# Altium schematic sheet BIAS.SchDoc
size A3; Date: Not shown in title block; ApprovedBy: Not shown in title block; CheckedBy: Not shown in title block; Author: Not shown in title block; CompanyName: Not shown in title block; Engineer: Not shown in title block; Organization: Not shown in title block; Address1: Not shown in title block; Address2: Not shown in title block; Address3: Not shown in title block; Address4: Not shown in title block; DocumentNumber: 1; Revision: Use project parameter SCH_Rev; SheetNumber: 3; SheetTotal: 3; PageSetup: Record=PageOptions¦CenterHorizontal=True¦CenterVertical=True¦PrintScale=0.93¦XCorrection=1.00¦YCorrection=1.00¦PrintKind=0¦BorderSize=5000000¦LeftOffset=0¦BottomOffset=0¦Orientation=2¦PaperLength=1000¦PaperWidth=1000¦Scale=100¦PaperSource=15¦PrintQuality=600¦MediaType=1¦DitherType=10¦PaperKind=Letter¦PrintScaleMode=1
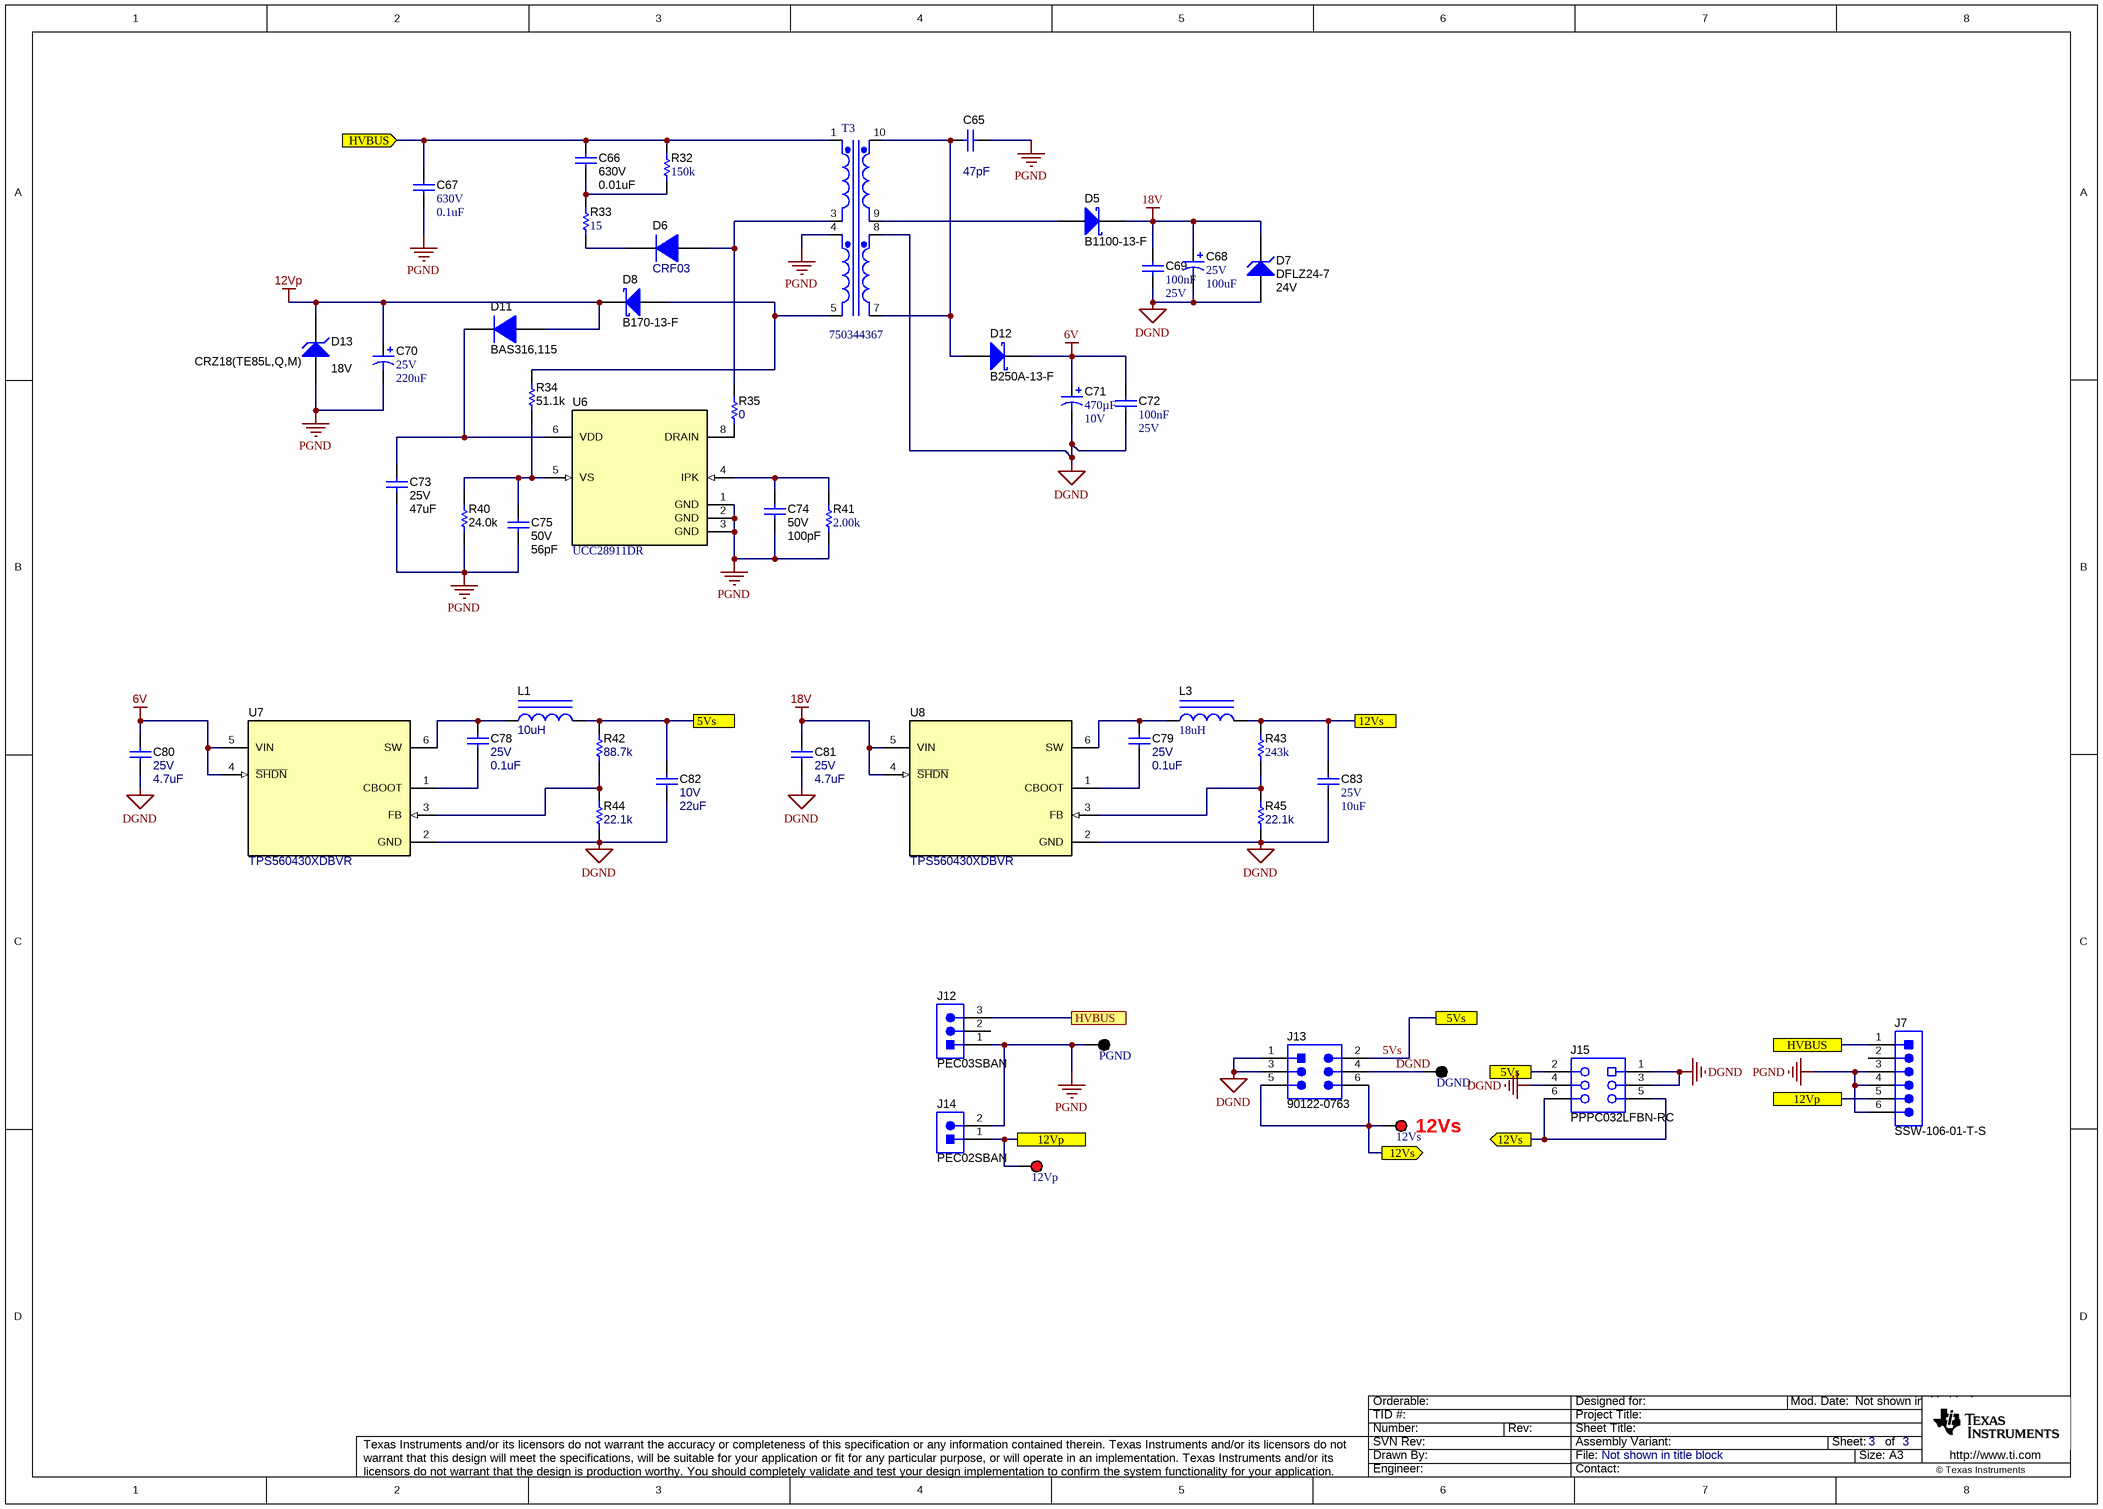
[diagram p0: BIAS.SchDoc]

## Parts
12Vp  5000  [Keystone5000]  (value not drawn)
12Vs  5000  [Keystone5000]  (value not drawn)
C65  ValueDisplayed: 47pF  [KY_700x500x1000]  (hidden comment: DE11XKX470JN4AC05F)
C66  VDC_V: 630V  ValueDisplayed: 0.01uF  [1206]  (hidden comment: GRM31BR72J103KW01L)
C67  VDC_V: 630V  ValueDisplayed: 0.1uF  [1210_280]  (hidden comment: C1210C104KBRAC7800)
C68  VDC_V: 25V  ValueDisplayed: 100uF  [SVPF_E7]  (hidden comment: 25SVPF100M)
C69  Cap_F: 100nF  VDC_V: 25V  [0603]  (hidden comment: GCJ188R71E104KA12D)
C70  VDC_V: 25V  ValueDisplayed: 220uF  [Panasonic_D8]  (hidden comment: EEEFTE221XAP)
C71  ValueDisplayed: 470µF  VDC_V: 10V  [Panasonic_D8]  (hidden comment: EEE-FTA471XAP)
C72  Cap_F: 100nF  VDC_V: 25V  [0603]  (hidden comment: GCJ188R71E104KA12D)
C73  VDC_V: 25V  ValueDisplayed: 47uF  [1206]  (hidden comment: C3216JB1E476M160AC)
C74  VDC_V: 50V  ValueDisplayed: 100pF  [0603]  (hidden comment: C0603C101J5GAC)  (no BOM)
C75  VDC_V: 50V  ValueDisplayed: 56pF  [0603]  (hidden comment: GRM1885C1H560JA01D)  (no BOM)
C78  VDC_V: 25V  ValueDisplayed: 0.1uF  [0603]  (hidden comment: C1608X7R1E104K080AA)
C79  VDC_V: 25V  ValueDisplayed: 0.1uF  [0603]  (hidden comment: C1608X7R1E104K080AA)
C80  VDC_V: 25V  ValueDisplayed: 4.7uF  [0603]  (hidden comment: GRM188R61E475KE11D)
C81  VDC_V: 25V  ValueDisplayed: 4.7uF  [0603]  (hidden comment: GRM188R61E475KE11D)
C82  VDC_V: 10V  ValueDisplayed: 22uF  [0603]  (hidden comment: C1608X5R1A226M080AC)
C83  VDC_V: 25V  ValueDisplayed: 10uF  [0603]  (hidden comment: GRT188R61E106ME13D)
D5  B1100-13-F  [SMA]
D6  CRF03  [SOD-123H]
D7  DFLZ24-7  value 24V  [PowerDI123]
D8  B170-13-F  [SMA]
D11  BAS316,115  [SOD-323]
D12  B250A-13-F  [SMA]
D13  CRZ18(TE85L,Q,M)  value 18V  [SOD-123]
DGND  5001  [Keystone5001]  (value not drawn)
J7  SSW-106-01-T-S  [Samtec_SSW-106-01-x-S]
J12  PEC03SBAN  [Sullins_PEC03SBAN]
J13  90122-0763  [Molex_90122-0763]
J14  PEC02SBAN  [Sullins_xxC02SBAN]
J15  PPPC032LFBN-RC  [Sullins_xxxC032LFBN-RC]
L1  ValueDisplayed: 10uH  [VLS252010HBX]  (hidden comment: 74438323100)
L3  ValueDisplayed: 18uH  [WE-PD2A_4532]  (hidden comment: 784773118)
PGND  5001  [Keystone5001]  (value not drawn)
R32  ValueDisplayed: 150k  [1206]  (hidden comment: CRCW1206150KFKEA)
R33  ValueDisplayed: 15  [0603]  (hidden comment: CRCW060315R0JNEA)
R34  ValueDisplayed: 51.1k  [0603]  (hidden comment: RC0603FR-0751K1L)
R35  ValueDisplayed: 0  [0603]  (hidden comment: RC0603JR-070RL)
R40  ValueDisplayed: 24.0k  [0603]  (hidden comment: RC0603FR-0724KL)
R41  ValueDisplayed: 2.00k  [0603]  (hidden comment: ERJ3EKF2001V)
R42  ValueDisplayed: 88.7k  [0603]  (hidden comment: CRCW060388K7FKEA)
R43  ValueDisplayed: 243k  [0603]  (hidden comment: RT0603BRD07243KL)
R44  ValueDisplayed: 22.1k  [0603]  (hidden comment: CRCW060322K1FKEA)
R45  ValueDisplayed: 22.1k  [0603]  (hidden comment: CRCW060322K1FKEA)
T3  750344367  [Wurth_750315894]
U6  UCC28911DR  [D0007A_N]
U7  TPS560430XDBVR  [DBV0006A_N]
U8  TPS560430XDBVR  [DBV0006A_N]

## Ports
5Vs, 12Vp, 12Vs, 12Vs (out), HVBUS, HVBUS (in)

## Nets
6V: C71.1(+) C72.1 C80.1 D12.1(K) U7.4(~{SHDN}) U7.5(VIN)
12Vp: C70.1(+) D8.1(K) D11.2(A) D13.1(K)
18V: C68.1(+) C69.1 C81.1 D5.1(K) D7.1(K) U8.4(~{SHDN}) U8.5(VIN)
DGND: C68.2(-) C69.2 C71.2(-) C72.2 C80.2 C81.2 C82.2 C83.2 D7.2(A) DGND.1 J13.1 J13.3 J13.4 J15.1 J15.3 J15.4 R44.1 R45.1 T3.8(Sec2+) U7.2(GND) U8.2(GND)
PGND: C65.2 C67.2 C70.2(-) C73.2 C74.2 C75.2 D13.2(A) J7.3 J7.4 J7.6 J12.1 J14.2 PGND.1 R40.1 R41.1 T3.4(Pri2+) U6.1(GND) U6.2(GND) U6.3(GND)
5Vs: C82.1 J13.2 J15.2 L1.2 R42.2 ; port 5Vs
12Vp: 12Vp.1 J7.5 J14.1 ; port 12Vp  [a separate net that carries the same name]
12Vs: 12Vs.1 C83.1 J13.5 J13.6 J15.5 J15.6 L3.2 R43.2 ; port 12Vs
HVBUS: C66.1 C67.1 J7.1 J12.3 R32.2 T3.1(Pri1+) ; port HVBUS
NetC65_1: C65.1 D12.2(A) T3.7(Sec2-) T3.10(Sec1+)
NetC66_2: C66.2 R32.1 R33.2
NetC73_1: C73.1 D11.1(K) U6.6(VDD)
NetC74_1: C74.1 R41.2 U6.4(IPK)
NetC75_1: C75.1 R34.1 R40.2 U6.5(VS)
NetC78_1: C78.1 L1.1 U7.6(SW)
NetC78_2: C78.2 U7.1(CBOOT)
NetC79_1: C79.1 L3.1 U8.6(SW)
NetC79_2: C79.2 U8.1(CBOOT)
NetD5_2: D5.2(A) T3.9(Sec1-)
NetD6_1: D6.1(K) R33.1
NetD6_2: D6.2(A) R35.2 T3.3(Pri1-)
NetD8_2: D8.2(A) R34.2 T3.5(Pri2-)
NetR35_1: R35.1 U6.8(DRAIN)
NetR42_1: R42.1 R44.2 U7.3(FB)
NetR43_1: R43.1 R45.2 U8.3(FB)

Not connected (* = marked no-connect by the designer): J7 2; J12 2

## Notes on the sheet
- 12Vs

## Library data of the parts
12Vp 12Vs = CMP-0055137-1: Test Point, Miniature, Red, TH; Manufacturer: Keystone; ContactFinish: Silver; Green_Lifecycle: Active; Green_REACh: Passed; CNHeader: FALSE; CT: TRUE
C65 = CMP-0009608-4: CAP, CERM, 47 pF, X1 250 VAC/Y1 300 VAC, +/- 10%, B, TH; Manufacturer: MuRata; TaMin_C: -25°C; Polarized: N; SizeAreaWB_mm2: 66.5; Value1: Unknown; U/M: EA; Value: 47pF; TaMax_C: 85°C; SizeZ_mm: 13; SizeX_mm: 9; SizeY_mm: 5; Cap_Case: 7x5x10mm; SizeArea_mm2: 37.5; AEC Category: Q200; AC_Safety: X1Y2; VAC_X: 250V; VAC_Y: 300V
C66 = CMP-0008910-2: CAP, CERM, 0.01 uF, 630 V, +/- 10%, X7R, 1206; Manufacturer: MuRata; TaMin_C: -55°C; Polarized: N; SizeAreaWB_mm2: 10.92; Value1: Unknown; U/M: EA; Value: 0.01uF; TaMax_C: 125°C; SizeZ_mm: 1.35; SizeX_mm: 3.2; SizeY_mm: 1.6; SizeArea_mm2: 5.12; Cap_F: 10nF; AEC Category: Q200
C67 = CMP-0009076-1: CAP, CERM, 0.1 uF, 630 V, +/- 10%, X7R, 1210; Manufacturer: Kemet; TaMin_C: -55°C; Polarized: N; SizeAreaWB_mm2: 14.7; Value1: Unknown; U/M: EA; Value: 0.1uF; TaMax_C: 125°C; SizeZ_mm: 2.8; SizeX_mm: 3.2; SizeY_mm: 2.5; Cap_Case: 1210; SizeArea_mm2: 8; Cap_F: 100nF; AEC Category: Q200
C68 = CMP-0012117-3: CAP, Aluminum Polymer, 100 uF, 25 V, +/- 20%, 0.024 ohm, 8.0x7.0mm SMD; Manufacturer: Panasonic; TaMin_C: -55°C; ESR_ohm: 24m; Polarized: Y; Value: 100uF; TaMax_C: 105°C; CompType: Capacitor; Cap_F: 100µF; IRMS_A: 3.2A; AEC Category: Q200
C69 C72 = CMP-0007404-4: CAP, CERM, 0.1 uF, 25 V, +/- 10%, X7R, 0603; Manufacturer: MuRata; TaMin_C: -55°C; Polarized: N; SizeAreaWB_mm2: 4.68; Value1: Unknown; U/M: EA; Value: 0.1uF; TaMax_C: 125°C; SizeZ_mm: 1; SizeX_mm: 1.6; SizeY_mm: 0.8; SizeArea_mm2: 1.28; AEC Category: Q200
C70 = CMP-0010738-1: CAP, AL, 220 uF, 25 V, +/- 20%, 0.16 ohm, AEC-Q200 Grade 2, SMD; Manufacturer: Panasonic; TaMin_C: -55°C; ESR_ohm: 0.16; Polarized: Y; SizeAreaWB_mm2: 73.96; U/M: EA; Value: 220uF; TaMax_C: 105°C; SizeZ_mm: 8; SizeX_mm: 6.6; Cap_Case: 6.3x7.7mm; SizeArea_mm2: 43.56; CompType: Capacitor; Cap_F: 220µF; IRMS_A: 600mA; AEC Grade: 2; AEC Category: Q200
C71 = CMP-0084632-1: CAP, AL, 470 µF, 10 V, +/- 20%, 0.16 ohm, AEC-Q200 Grade 2, SMD; Manufacturer: Panasonic; U/M: EA; SizeArea_mm2: 43.56; ESR_ohm: 0.16; AEC Category: Q200; SizeY_mm: 6.6; Value: 470uF; TaMin_C: -55°C; TaMax_C: 105°C; SizeAreaWB_mm2: 73.96; CompType: Capacitor; AEC Qualified: Y; Cap_Case: 6.6x6.6x8mm; AEC Grade: 2; SizeZ_mm: 8
C73 = CMP-0008646-2: CAP, CERM, 47 uF, 25 V, +/- 20%, JB, 1206; Manufacturer: TDK; TaMin_C: -55°C; Polarized: N; SizeAreaWB_mm2: 10.92; Value1: Unknown; U/M: EA; Value: 47uF; TaMax_C: 85°C; SizeZ_mm: 1.35; SizeX_mm: 3.2; SizeY_mm: 1.6; SizeArea_mm2: 5.12; Cap_F: 47µF; AEC Category: Q200
C74 = CMP-0006840-4: CAP, CERM, 100 pF, 50 V, +/- 5%, C0G/NP0, 0603; Manufacturer: Kemet; TaMin_C: -55°C; Polarized: N; SizeAreaWB_mm2: 4.68; Value1: Unknown; U/M: EA; Value: 100pF; TaMax_C: 125°C; SizeZ_mm: 1; SizeX_mm: 1.6; SizeY_mm: 0.8; SizeArea_mm2: 1.28; AEC Category: Q200
C75 = CMP-0007224-4: CAP, CERM, 56 pF, 50 V, +/- 5%, C0G/NP0, 0603; Manufacturer: MuRata; TaMin_C: -55°C; Polarized: N; SizeAreaWB_mm2: 4.68; Value1: Unknown; U/M: EA; Value: 56pF; TaMax_C: 125°C; SizeZ_mm: 1; SizeX_mm: 1.6; SizeY_mm: 0.8; SizeArea_mm2: 1.28; AEC Category: Q200
C78 C79 = CMP-0007039-5: CAP, CERM, 0.1 uF, 25 V, +/- 10%, X7R, 0603; Manufacturer: TDK; TaMin_C: -55°C; Polarized: N; SizeAreaWB_mm2: 4.68; Value1: Unknown; U/M: EA; Value: 0.1uF; TaMax_C: 125°C; SizeZ_mm: 1; SizeX_mm: 1.6; SizeY_mm: 0.8; SizeArea_mm2: 1.28; Cap_F: 100nF; AEC Category: Q200
C80 C81 = CMP-0007347-1: CAP, CERM, 4.7 uF, 25 V, +/- 10%, X5R, 0603; Manufacturer: MuRata; TaMin_C: -55°C; Polarized: N; SizeAreaWB_mm2: 4.68; Value1: Unknown; U/M: EA; Value: 4.7uF; TaMax_C: 85°C; SizeZ_mm: 1; SizeX_mm: 1.6; SizeY_mm: 0.8; SizeArea_mm2: 1.28; Cap_F: 4.7µF; AEC Category: Q200
C82 = CMP-0007005-1: CAP, CERM, 22 uF, 10 V, +/- 20%, X5R, 0603; Manufacturer: TDK; TaMin_C: -55°C; ESR_ohm: 3.71m; Polarized: N; SizeAreaWB_mm2: 4.68; Value1: 0.00371 ohm; U/M: EA; Value: 22uF; TaMax_C: 85°C; SizeZ_mm: 1; SizeX_mm: 1.6; SizeY_mm: 0.8; SizeArea_mm2: 1.28; Cap_F: 22µF; IRMS_A: 2.69936A; AEC Category: Q200
C83 = CMP-0007501-4: CAP, CERM, 10 uF, 25 V, +/- 20%, X5R, 0603; Manufacturer: MuRata; TaMin_C: -55°C; Polarized: N; SizeAreaWB_mm2: 4.68; Value1: Unknown; U/M: EA; Value: 10uF; TaMax_C: 85°C; SizeZ_mm: 1; SizeX_mm: 1.6; SizeY_mm: 0.8; SizeArea_mm2: 1.28; Cap_F: 10µF; AEC Category: Q200
D5 = CMP-0028371-1: Diode, Schottky, 100 V, 1 A, SMA; Manufacturer: Diodes Inc.; Io_A: 1A; Green_Lifecycle: Active; SizeAreaWB_mm2: 37.3428; Vr_V: 100V; Green_REACh: Passed; TJmax_C: 150°C; U/M: EA; Value: 100V; SizeZ_mm: 2.87; SizeX_mm: 5.59; SizeY_mm: 2.92; Vf_V: 790mV; Value2: 0.79V; SizeArea_mm2: 16.3228; AEC Category: Q101; RJC_CperW: 25
D6 = CMP-0077074-2: Diode, Superfast Rectifier, 600 V, 1 A, 3.5x1.6mm; Manufacturer: Toshiba; Value: 600V; SizeY_mm: 1.6; Value2: 1.7V; Value1: 1A; Io_A: 0.7A; Green_Lifecycle: Not Set; AEC Category: Q101; SizeX_mm: 3.5; SizeAreaWB_mm2: 11.7; SizeZ_mm: 1.0; Green_REACh: Incomplete; SizeArea_mm2: 5.6; TJmax_C: 150°C; AEC Qualified: N
D7 = CMP-0005415-4: Diode, Zener, 24 V, 1 W, PowerDI123; Manufacturer: Diodes Inc.; Power_W: 1W; RJA_CperW: 110; SizeAreaWB_mm2: 13.066; SizeZ_mm: 0.98; SizeX_mm: 3.7; AEC Category: Q101; SizeY_mm: 1.78; SizeArea_mm2: 6.586
D8 = CMP-0028391-2: Diode, Schottky, 70 V, 1 A, SMA; Manufacturer: Diodes Inc.; SizeAreaWB_mm2: 37.3428; RJC_CperW: 25; Io_A: 1A; AEC Category: Q101; Green_Lifecycle: Active; SizeZ_mm: 2.87; Value: 70V; Vf_V: 7.9dV; SizeY_mm: 2.92; Green_REACh: Passed; Value2: 0.79V; SizeX_mm: 5.59; TJmax_C: 150°C; SizeArea_mm2: 16.3228
D11 = CMP-0029006-1: Diode, Ultrafast, 100 V, 0.25 A, SOD-323; Manufacturer: Nexperia; Io_A: 250mA; Green_Lifecycle: Not Set; SizeAreaWB_mm2: 8.695; Vr_V: 100V; Green_REACh: Incomplete; Value1: 0.25A; TJmax_C: 150°C; U/M: EA; Value: 100V; SizeZ_mm: 1; SizeX_mm: 2.7; SizeY_mm: 1.35; Vf_V: 1.4V; SizeArea_mm2: 3.645; AEC Category: Q101
D12 = CMP-0028405-2: Diode, Schottky, 50 V, 2 A, SMA; Manufacturer: Diodes Inc.; SizeArea_mm2: 16.3228; RJC_CperW: 20; Vr_V: 50V; SizeX_mm: 5.59; Green_REACh: Incomplete; SizeY_mm: 2.92; Green_Lifecycle: Not Set; Value2: 0.7V; Io_A: 2A; Value: 50V; SizeZ_mm: 2.87; SizeAreaWB_mm2: 37.3428; AEC Category: Q101; TJmax_C: 150°C; Vf_V: 7dV
D13 = CMP-0005747-4: Diode, Zener, 18 V, 700 mW, SOD-123; Manufacturer: Toshiba; SizeAreaWB_mm2: 13.095; SizeArea_mm2: 6.545; SizeX_mm: 3.85; Value1: 0.7W; SizeY_mm: 1.7; Power_W: 700mW; SizeZ_mm: 1.35; RJA_CperW: 340; AEC Category: Q101
DGND PGND = CMP-0055138-1: Test Point, Miniature, Black, TH; Manufacturer: Keystone; ContactFinish: Silver; Green_Lifecycle: Active; Green_REACh: Passed; CNHeader: FALSE; CT: TRUE
J7 = CMP-0075621-1: Receptacle, 6x1, 2.54mm, Tin, TH; Manufacturer: Samtec; Pitch_mm: 2.54; Gender: Female; Cert_CSA: Y; Current_A: 5.7A; CT: False; Row_Count: 1
J12 = CMP-0054704-1: Header, 100mil, 3x1, Tin, R/A, TH; Manufacturer: Sullins Connector Solutions; CNHeader: FALSE; Current_A: 3A; Green_Lifecycle: Not Set; Shrouded: N; Gender: Male; Green_REACh: Incomplete; Voltage_V: 1.8kV; Row_Count: 1; Pitch_mm: 2.54; Cert_UL: Y
J13 = CMP-0077741-2: Header, 2.54mm, 3x2, Gold, R/A, TH; Manufacturer: Molex; Pitch_mm: 2.54; Gender: Male; Cert_UL: Y; Current_A: 3A; Voltage_V: 350V; Shrouded: N; Row_Count: 2
J14 = CMP-0054712-1: Header, 2.54 mm, 2x1, Tin, R/A, TH; Manufacturer: Sullins Connector Solutions; CNHeader: FALSE; Current_A: 3A; Shrouded: N; Gender: Male; Voltage_V: 1.8kV; Row_Count: 1; Pitch_mm: 2.54; Cert_UL: Y
J15 = CMP-0082513-1: Receptacle, 2.54mm, 3x2, Gold, TH; Manufacturer: Sullins Connector Solutions; Pitch_mm: 2.54; Gender: Female; Cert_UL: Y; Voltage_V: 250V; Current_A: 3A; Row_Count: 2; CompType: Socket Strip
L1 = CMP-0063086-1: Inductor, Wirewound, Ferrite, 10 uH, 0.68 A, 0.46 ohm, SMD; Manufacturer: Würth Elektronik; Isat: 1.35A @ 20% inductance drop; Irms: 0.60A @ 40C rise; Green_Lifecycle: Active; SizeAreaWB_mm2: 10.5; DCR_ohm: 0.46; Green_REACh: Passed; Value1: 0.843 ohm; Value: 10uH; Imax_A: 600mA; SizeZ_mm: 1; SizeX_mm: 2.5; SizeY_mm: 2; Value2: 0.6A; SizeArea_mm2: 5; Ind_H: 10µH; AEC Qualified: N; AEC Category: Q200
L3 = CMP-0064687-1: Inductor, Wirewound, Ferrite, 18 uH, 1.1 A, 0.225 ohm, AEC-Q200 Grade 1, SMD; Manufacturer: Wurth Elektronik; Isat: 1.29A @ 20% inductance drop; Irms: 1.1A @ 40C rise; Green_Lifecycle: Active; SizeAreaWB_mm2: 27.5; DCR_ohm: 0.225; Green_REACh: Passed; Value: 18uH; Imax_A: 1.1A; SizeZ_mm: 3.5; SizeX_mm: 4; SizeY_mm: 4.5; SizeArea_mm2: 18; Ind_H: 18µH; AEC Qualified: Y; AEC Grade: 1; AEC Category: Q200
R32 = CMP-0016639-3: RES, 150 k, 1%, 0.25 W, AEC-Q200 Grade 0, 1206; Manufacturer: Vishay-Dale; Power_W: 250mW; TempCo: 100 ppm/C; Value: 150k; EIA_Code: E96; SizeX_mm: 3.2; SizeY_mm: 1.6; SizeZ_mm: 1.35; Value2: 0.25W; SizeArea_mm2: 5.12; AEC Qualified: Y; VDC_V: 200V; AEC Category: Q200; AEC Grade: 0
R33 = CMP-0025720-4: RES, 15, 5%, 0.1 W, AEC-Q200 Grade 0, 0603; Manufacturer: Vishay-Dale; Power_W: 100mW; TempCo: 200 ppm/C; Value_Code: 15R0; Value: 15; EIA_Code: E24; SizeX_mm: 1.6; SizeY_mm: 0.8; SizeZ_mm: 1; Value2: 0.1W; SizeArea_mm2: 1.28; AEC Qualified: Y; VDC_V: 75V; AEC Category: Q200; AEC Grade: 0
R34 = CMP-0023166-5: RES, 51.1 k, 1%, 0.1 W, 0603; Manufacturer: Yageo; Power_W: 100mW; TempCo: 100 ppm/C; Value_Code: 51k1; Value: 51.1k; EIA_Code: E96; SizeX_mm: 1.6; SizeY_mm: 0.8; SizeZ_mm: 1; Value2: 0.1W; SizeArea_mm2: 1.28; AEC Qualified: N; VDC_V: 75V; AEC Category: Q200; SizeAreaWB_mm2: 4.68
R35 = CMP-0025885-5: RES, 0, 5%, 0.1 W, 0603; Manufacturer: Yageo; Power_W: 100mW; TempCo: 200 ppm/C; Value_Code: 0000; Value: 0; EIA_Code: E24; SizeX_mm: 1.6; SizeZ_mm: 1; Value2: 0.1W; SizeArea_mm2: 1.28; AEC Qualified: N; VDC_V: 75V; AEC Category: Q200; SizeY_mm: 0.8; SizeAreaWB_mm2: 4.68
R40 = CMP-0022945-5: RES, 24.0 k, 1%, 0.1 W, 0603; Manufacturer: Yageo; Power_W: 100mW; TempCo: 100 ppm/C; Value_Code: 24k0; Value: 24.0k; Res_ohm: 24k; SizeX_mm: 1.6; SizeY_mm: 0.8; SizeZ_mm: 1; Value2: 0.1W; SizeArea_mm2: 1.28; AEC Qualified: N; VDC_V: 75V; AEC Category: Q200; SizeAreaWB_mm2: 4.68
R41 = CMP-0078663-1: RES, 2.00 k, 1%, 0.1 W, AEC-Q200 Grade 0, 0603; Manufacturer: Panasonic; Power_W: 100mW; TempCo: 100 ppm/C; Value_Code: 2k00; Value: 2.00k; EIA_Code: E96; Res_ohm: 2k; SizeX_mm: 1.6; SizeY_mm: 0.8; SizeZ_mm: 1; Value2: 0.1W; SizeArea_mm2: 1.28; AEC Qualified: Y; AEC Grade: 0; AEC Category: Q200
R42 = CMP-0022632-1: RES, 88.7 k, 1%, 0.1 W, 0603; Manufacturer: Vishay-Dale; Power_W: 100mW; TempCo: 100 ppm/C; Value_Code: 88k7; U/M: EA; Value: 88.7k; EIA_Code: E96; SizeX_mm: 1.6; SizeY_mm: 0.8; SizeZ_mm: 1; Value2: 0.1W; SizeArea_mm2: 1.28; VDC_V: 75V; AEC Category: Q200
R43 = CMP-0023982-2: RES, 243 k, 0.1%, 0.1 W, 0603; Manufacturer: Yageo America; Power_W: 100mW; TempCo: 25 ppm/C; U/M: EA; Value: 243k; EIA_Code: E192; SizeX_mm: 1.6; SizeY_mm: 0.8; SizeZ_mm: 1; Value2: 0.1W; SizeArea_mm2: 1.28; VDC_V: 75V; AEC Category: Q200
R44 R45 = CMP-0022220-1: RES, 22.1 k, 1%, 0.1 W, 0603; Manufacturer: Vishay-Dale; Power_W: 100mW; TempCo: 100 ppm/C; Value_Code: 22k1; U/M: EA; Value: 22.1k; EIA_Code: E96; SizeX_mm: 1.6; SizeY_mm: 0.8; SizeZ_mm: 1; Value2: 0.1W; SizeArea_mm2: 1.28; VDC_V: 75V; AEC Category: Q200
T3 = Trans BB: flyback transformer for UCC28911 dual output; Manufacturer: Wurth Elektronik
U6 = CMP-0074093-2: 700V Flyback Switcher with Constant-Voltage Constant-Current and Primary-side Regulation, D0007A (SOIC-7); Alternate Manufacturer: Texas Instruments; SizeAreaWB_mm2: 55.2; U/M: EA; SizeZ_mm: 1.75; SizeX_mm: 6.0; SizeY_mm: 4.9; SizeArea_mm2: 29.4; CompType: IC; AEC Category: Q200; AEC Qualified: N
U7 U8 = CMP-0065097-1: 4V to 36 V 0.6 A Synchronous Step-Down Converter, DBV0006A (SOT-23-6); Alternate PartNumber: TPS560430XDBVT; Alternate Manufacturer: Texas Instruments; SizeAreaWB_mm2: 14.82; U/M: EA; SizeZ_mm: 1.45; SizeX_mm: 2.8; SizeY_mm: 2.9; SizeArea_mm2: 8.12; CompType: IC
